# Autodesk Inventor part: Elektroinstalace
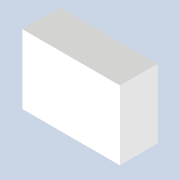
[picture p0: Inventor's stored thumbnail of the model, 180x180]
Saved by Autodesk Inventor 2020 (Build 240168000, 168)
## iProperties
Created: 2025-03
Part Number: Elektroinstalace
Material: Polypropylen
Document SubType Name: Modeling
Designer: doma
Density: 0.899 g/cm^3
Appearance: Hladká – bílá
Author: doma
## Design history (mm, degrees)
sketch "Náčrt1"
  geometry: L1 (-155, -110)-(155, -110); L2 (155, -110)-(155, 110); L3 (155, 110)-(-155, 110); L4 (-155, 110)-(-155, -110); L5 (-155, -110)-(155, 110); L6 (155, -110)-(-155, 110); 1 further point
  constraints: 12 end point, 2 midpoint, 2 parallel, 1 horizontal, 1 perpendicular
  dimensions: "d0" = 310 distance of L3.end L2.end; "d1" = 220 distance of L2.end L1.end
extrude "Vysunutí1" new body sketch "Náčrt1" distance "d2" = 120; taper "d3" = 0 deg
feature "Skořepina1" dims "d4" = 5
sketch "Náčrt2"
  geometry: L1 (0, 0)-(0, 120) reference; L2 (0, 120)-(310, 120) reference; L3 (310, 0)-(310, 120) reference; C1 r 12.5 at (50, 30); C2 r 12.5 at (260, 30); C3 r 12.5 at (201.899, 30); 1 further point
  constraints: 3 centre point
  dimensions: "d5" = 25 diameter of C1; "d8" = 25 diameter of C2; "d11" = 50 distance from line of L1 C1.centre; "d12" = 90 distance from line of L2 C1.centre; "d13" = 90 distance from line of L2 C2.centre (= d12); "d15" = 50 distance from line of L3 C2.centre (= d11); "d16" = 25 diameter of C3
extrude "Vysunutí2" join sketch "Náčrt2" distance "d9" = 20; taper "d10" = 0 deg
node "Těleso1"
